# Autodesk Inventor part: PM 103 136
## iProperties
Shininess: 20.0
Length Units: 11269
Angle Units: 11279
Time Units: 11290
Mass Units: 11283
Length Display Precision: 3
Angle Display Precision: 2
Created: 2003-05
Part Number: PM 103 136
Material: Kupfer
Document SubType Name: Modellieren
Designer: PEISLER
Manufacturer: Standard
Standards Organization: Custom
Density: 0.0
Volumn: 0.0
Area: 0.0
PropertySet Name: Model Information
Control State: 0
Master: False
Checked Out: False
Abt: EK
Ausgangsteil: N 1928 085 KH
KB: Ts
Werkstoffbez: Rohr, SF-Cu / F30  10x1
ZK: We
Datum: 03-05-27
Allgtol: DIN ISO 2768-mH
Aussenkante: 0-0.2 gratfrei
Innenkante: 0-0.5 Übergang
Tolerierung: DIN 7167
Werkstkante: DIN 6784
Author: PEISLER
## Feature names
1. Sweeping2
